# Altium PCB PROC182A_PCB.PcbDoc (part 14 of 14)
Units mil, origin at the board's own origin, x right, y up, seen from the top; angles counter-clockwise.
Board outline 3168.31 x 3700.79 mil, 8 copper layers (Top Layer, L2_GND1, L3_SIG1, L4_PWR1, L5_PWR2, L6_SIG2, L7_GND2, Bottom Layer), stack 58.1 mil thick; 580 components, 391 nets, 8314 pads, 4370 vias.
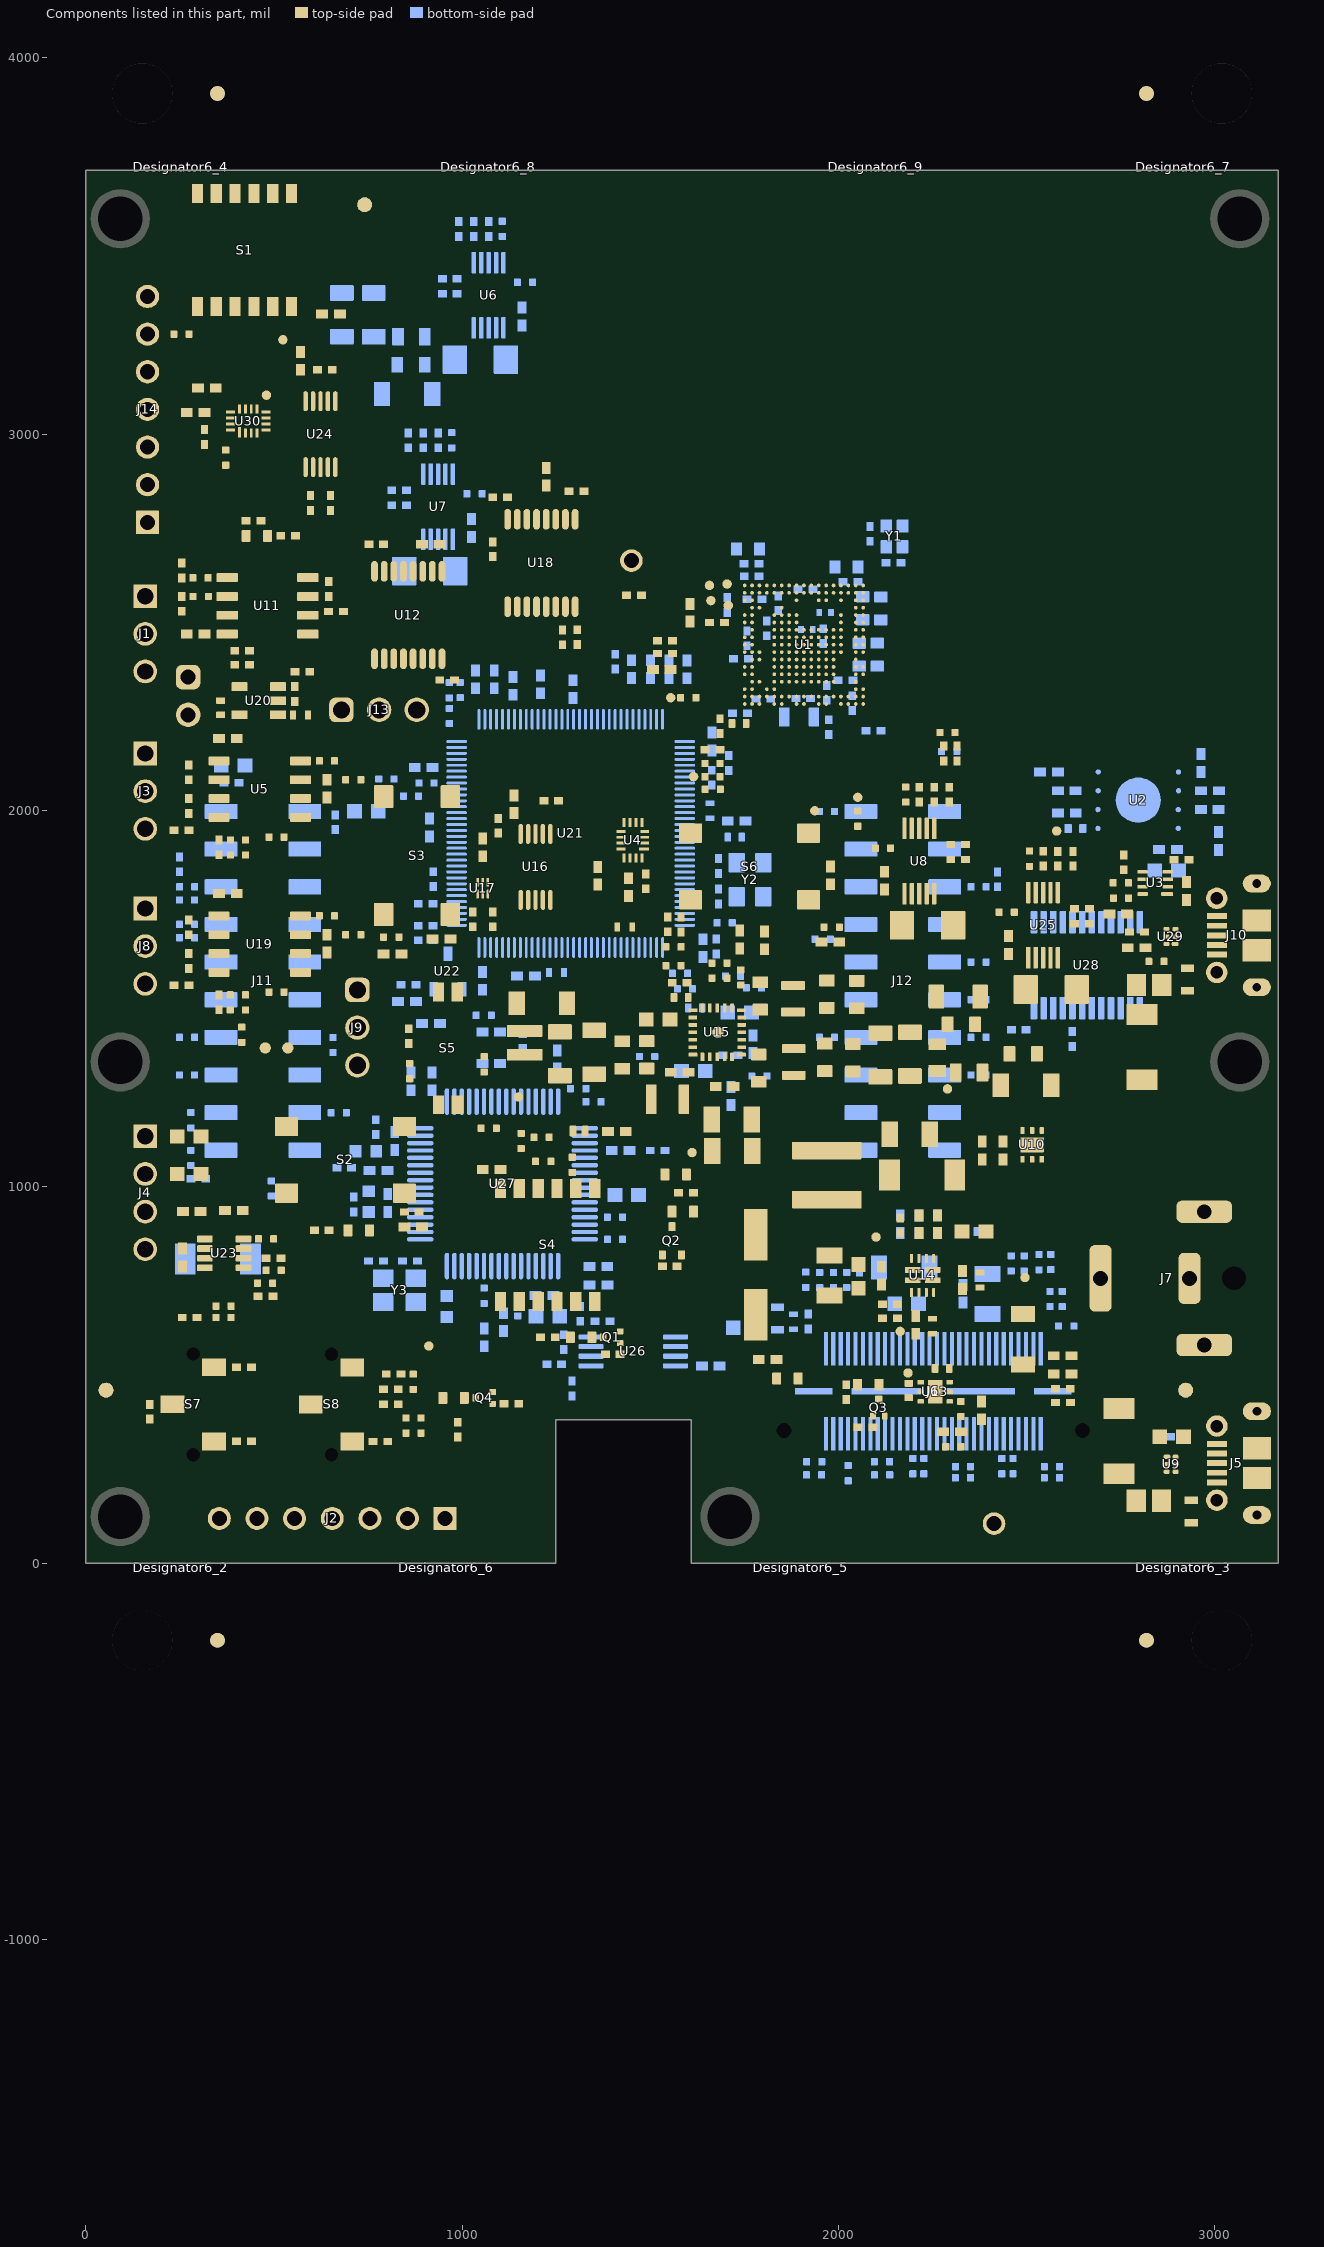
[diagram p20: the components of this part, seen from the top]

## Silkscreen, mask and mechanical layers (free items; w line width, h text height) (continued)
M12 Stackup:
  drawing of 601 lines, arcs and shapes, not listed
  text "NOTE :" at 8331.23,7827.52 h60
  text "1. THIS IS AN IMPEDANCE CONTROLLED BOARD." at 8328.85,7700.44 h60
  text "2. EXTERNAL LAYER CU THICKNESSES ARE FINISHED THICKNESS AFTER PLATING." at 8328.85,7602.57 h60
  text "6" at 10048.98,7447.87 h60
  text "IMPEDANCE TABLE :" at 8892.6,7432.49 h80
  text "LAYER" at 8390.84,7323.14 h70
  text "TRACE WIDTH" at 8678.04,7322.3 h70
  text "SPACING" at 9163.04,7322.3 h70
  text "IMPEDANCE +/- 10%" at 9498.04,7322.3 h70
  text "REFERENCE LAYER" at 10223.04,7322.3 h70
  text "TOP" at 8457.92,7164.16 h70
  text "3.944 MILS" at 9157.24,7164.14 h65
  text "8.386 MILS" at 8742.92,7159.16 h65
  text "50 OHM" at 9617.92,7159.16 h65
  text "LAYER-2 (GND LAYER)" at 10182.92,7159.16 h65
  text "LAYER" at 8389.87,6945.5 h70
  text "TRACE WIDTH" at 8677.07,6944.65 h70
  text "SPACING" at 9162.07,6944.65 h70
  text "IMPEDANCE +/- 10%" at 9497.07,6944.65 h70
  text "REFERENCE LAYER" at 10222.07,6944.65 h70
  text "10.8 MILS" at 8769.81,6782.42 h65
  text "-" at 9289.75,6778.3 h65
  text "LAYER-2" at 10381.3,6776.48 h65
  text "50 OHM" at 9648.9,6773.59 h65
  text "TOP" at 8420.36,6759.04 h70
  text "LAYER-7" at 10376.33,6601.76 h65
  text "-" at 9286.8,6590.31 h65
  text "8.7 MILS" at 8755.67,6583.5 h65
  text "BOTTOM" at 8366.78,6581.81 h60
  text "50 OHM" at 9646.57,6581 h65
  text "6 MILS" at 8757.91,6404.23 h65
  text "50 OHM" at 9646.63,6396.36 h65
  text "L3 & L6" at 8377.39,6392.24 h70
  text "LAYER-2, LAYER 7" at 10253.41,6385.32 h65
  text "LAYER-2" at 10361.75,6229.75 h65
  text "TOP" at 8400.79,6222.36 h70
  text "7.5 MILS" at 8760.59,6212.35 h65
  text "90 OHM" at 9652.66,6211.89 h65
  text "4 MILS" at 9193.85,6210.67 h65
  text "6 MILS" at 8791.86,6049.13 h65
  text "90 OHM" at 9656.08,6044.32 h65
  text "LAYER-7" at 10381.73,6044.87 h65
  text "5 MILS" at 9201.69,6041.6 h65
  text "BOTTOM" at 8396.22,6027.98 h60
  text "5 MILS" at 8790.62,5867.91 h65
  text "90 OHM" at 9662.73,5857.78 h65
  text "5.9 MILS" at 9190.11,5853.43 h65
  text "L3" at 8434.55,5841.85 h70
  text "LAYER-2, LAYER 4" at 10229.8,5836.19 h65
  text "TOP" at 8409.33,5680.06 h70
  text "4.3 MILS" at 8769.14,5670.06 h65
  text "120 OHM" at 9661.21,5669.59 h65
  text "5.5 MILS" at 9202.4,5668.37 h65
  text "LAYER-2" at 10364.71,5659.53 h65
  text "TOP" at 8400.79,5482.36 h70
  text "5.8 MILS" at 8749.74,5477.02 h65
  text "4.2 MILS" at 9183.36,5473.81 h65
  text "100 OHM" at 9641.52,5466.83 h65
  text "LAYER-2" at 10367.12,5465.77 h65
  text "5.9 MILS" at 8752.96,5297.15 h65
  text "100 OHM" at 9634.62,5296.37 h65
  text "3.9 MILS" at 9176.94,5290.72 h65
  text "BOTTOM" at 8396.22,5287.98 h60
  text "LAYER-7" at 10365.97,5283.38 h65
  text "LAYER-2, LAYER 4" at 10252.53,5110.69 h65
  text "L3" at 8434.55,5101.85 h70
  text "4.8 MILS" at 8752.96,5101.21 h65
  text "100 OHM" at 9631.41,5100.44 h65
  text "7.2 MILS" at 9173.73,5088.37 h65
  text "LAYER STACK-UP :" at 3968.15,2059.49 h80
  text "Layer" at 4024.78,1866.38 h60
  text "Name" at 4434.69,1866.38 h60
  text "Material" at 5364.44,1866.38 h60
  text "Thickness" at 6224.2,1866.38 h60
  text "Constant" at 6874.04,1866.38 h60
  text "Board Layer Stack" at 7443.9,1866.38 h60
  text "Top Overlay" at 4434.69,1746.38 h60
  text "Top Solder" at 4434.69,1626.38 h60
  text "Solder Resist" at 5364.44,1626.38 h60
  text "0.80mil" at 6224.2,1626.38 h60
  text "1" at 6874.04,1626.38 h60
  text "1" at 4024.78,1506.38 h60
  text "Top Layer" at 4434.69,1506.38 h60
  text "1.60mil" at 6224.2,1506.38 h60
  text "Dielectric 1" at 4434.69,1386.38 h60
  text "RO3003" at 5364.44,1386.38 h60
  text "5.00mil" at 6224.2,1386.38 h60
  text "3" at 6874.04,1386.38 h60
  text "2" at 4024.78,1266.38 h60
  text "L2_GND1" at 4434.69,1266.38 h60
  text "1.40mil" at 6224.2,1266.38 h60
  text "Dielectric 2" at 4434.69,1146.38 h60
  text "PCL370HR" at 5364.44,1146.38 h60
  text "5.50mil" at 6224.2,1146.38 h60
  text "3.9" at 6874.04,1146.38 h60
  text "3" at 4024.78,1026.38 h60
  text "L3_SIG1" at 4434.69,1026.38 h60
  text "1.40mil" at 6224.2,1026.38 h60
  text "Dielectric 3" at 4434.69,906.38 h60
  text "PCL370HR" at 5364.44,906.38 h60
  text "10.00mil" at 6224.2,906.38 h60
  text "4.25" at 6874.04,906.38 h60
  text "4" at 4024.78,786.38 h60
  text "L4_PWR1" at 4434.69,786.38 h60
  text "1.40mil" at 6224.2,786.38 h60
  text "Dielectric 4" at 4434.69,666.38 h60
  text "PCL370HR" at 5364.44,666.38 h60
  text "5.50mil" at 6224.2,666.38 h60
  text "3.9" at 6874.04,666.38 h60
  text "5" at 4024.78,546.38 h60
  text "L5_PWR2" at 4434.69,546.38 h60
  text "1.40mil" at 6224.2,546.38 h60
  text "Dielectric 5" at 4434.69,426.38 h60
  text "PCL370HR" at 5364.44,426.38 h60
  text "10.00mil" at 6224.2,426.38 h60
  text "4.25" at 6874.04,426.38 h60
  text "6" at 4024.78,306.38 h60
  text "L6_SIG2" at 4434.69,306.38 h60
  text "1.40mil" at 6224.2,306.38 h60
  text "Dielectric 6" at 4434.69,186.38 h60
  text "PCL370HR" at 5364.44,186.38 h60
  text "5.50mil" at 6224.2,186.38 h60
  text "3.9" at 6874.04,186.38 h60
  text "7" at 4024.78,66.38 h60
  text "L7_GND2" at 4434.69,66.38 h60
  text "1.40mil" at 6224.2,66.38 h60
  text "Dielectric 7" at 4434.69,-53.62 h60
  text "PCL370HR" at 5364.44,-53.62 h60
  text "5.00mil" at 6224.2,-53.62 h60
  text "4.25" at 6874.04,-53.62 h60
  text "8" at 4024.78,-173.62 h60
  text "Bottom Layer" at 4434.69,-173.62 h60
  text "1.60mil" at 6224.2,-173.62 h60
  text "Bottom Solder" at 4434.69,-293.62 h60
  text "Solder Resist" at 5364.44,-293.62 h60
  text "0.80mil" at 6224.2,-293.62 h60
  text "1" at 6874.04,-293.62 h60
  text "Bottom Overlay" at 4434.69,-413.62 h60
  text ".Layer_Name" at 186.57,-874.24 h60
M13 Component Bodies Top:
  text ".Layer_Name" at 186.57,-874.24 h60
M14 Component Bodies Bottom:
  text ".Layer_Name" at 186.57,-874.24 h60
M15 Courtyards Top:
  text ".Layer_Name" at 186.57,-874.24 h60
M16 Courtyards Bottom:
  text ".Layer_Name" at 186.57,-874.24 h60
Drill Drawing:
  drawing of 199 lines, arcs and shapes, not listed
  text "Symbol" at -553.46,7687.3 h75.59
  text "Count" at -23.93,7687.3 h75.59
  text "Hole Size" at 667.82,7687.3 h75.59
  text "Plated" at 1747.91,7687.3 h75.59
  text "Hole Type" at 2277.43,7687.3 h75.59
  text "Drill Layer Pair" at 3046.26,7687.3 h75.59
  text "Hole Tolerance (+)" at 4315.27,7687.3 h75.59
  text "Hole Tolerance (-)" at 5713.83,7687.3 h75.59
  text "3453" at -23.93,7529.82 h62.99
  text "7.00mil (0.178mm)" at 667.82,7529.82 h62.99
  text "PTH" at 1747.91,7529.82 h62.99
  text "Round" at 2277.43,7529.82 h62.99
  text "Top Layer - L2_GND1" at 3046.26,7529.82 h62.99
  text "0.00mil (0.000mm)" at 4315.27,7529.82 h62.99
  text "0.00mil (0.000mm)" at 5713.83,7529.82 h62.99
  text "3453 Total" at -23.93,7372.33 h62.99
  text "Symbol" at -528.63,7262.14 h71.39
  text "Count" at -26.74,7262.14 h71.39
  text "Hole Size" at 617.79,7262.14 h71.39
  text "Hole Length" at 1757.95,7262.14 h71.39
  text "Plated" at 2868.38,7262.14 h71.39
  text "Hole Type" at 3370.27,7262.14 h71.39
  text "Drill Layer Pair" at 4098.17,7262.14 h71.39
  text "Hole Tolerance (+)" at 5585.29,7262.14 h71.39
  text "Hole Tolerance (-)" at 6907.95,7262.14 h71.39
  text "2" at -26.74,7113.4 h59.5
  text "7.87mil (0.200mm)" at 617.79,7113.4 h59.5
  text "-" at 1757.95,7113.4 h59.5
  text "PTH" at 2868.38,7113.4 h59.5
  text "Round" at 3370.27,7113.4 h59.5
  text "Top Layer - Bottom Layer" at 4098.17,7113.4 h59.5
  text "4" at -26.74,6964.66 h59.5
  text "7.87mil (0.200mm)" at 617.79,6964.66 h59.5
  text "-" at 1757.95,6964.66 h59.5
  text "PTH" at 2868.38,6964.66 h59.5
  text "Round" at 3370.27,6964.66 h59.5
  text "Top Layer - Bottom Layer" at 4098.17,6964.66 h59.5
  text "3.00mil (0.076mm)" at 5585.29,6964.66 h59.5
  text "3.00mil (0.076mm)" at 6907.95,6964.66 h59.5
  text "911" at -26.74,6815.92 h59.5
  text "8.00mil (0.203mm)" at 617.79,6815.92 h59.5
  text "-" at 1757.95,6815.92 h59.5
  text "PTH" at 2868.38,6815.92 h59.5
  text "Round" at 3370.27,6815.92 h59.5
  text "Top Layer - Bottom Layer" at 4098.17,6815.92 h59.5
  text "3.00mil (0.076mm)" at 5585.29,6815.92 h59.5
  text "3.00mil (0.076mm)" at 6907.95,6815.92 h59.5
  text "24" at -26.74,6667.19 h59.5
  text "19.69mil (0.500mm)" at 617.79,6667.19 h59.5
  text "-" at 1757.95,6667.19 h59.5
  text "NPTH" at 2868.38,6667.19 h59.5
  text "Round" at 3370.27,6667.19 h59.5
  text "Top Layer - Bottom Layer" at 4098.17,6667.19 h59.5
  text "A" at -557.54,6657.2 h66.11
  text "4" at -26.74,6518.45 h59.5
  text "23.62mil (0.600mm)" at 617.79,6518.45 h59.5
  text "51.18mil (1.300mm)" at 1757.95,6518.45 h59.5
  text "PTH" at 2868.38,6518.45 h59.5
  text "Slot" at 3370.27,6518.45 h59.5
  text "Top Layer - Bottom Layer" at 4098.17,6518.45 h59.5
  text "3.00mil (0.076mm)" at 5585.29,6518.45 h59.5
  text "3.00mil (0.076mm)" at 6907.95,6518.45 h59.5
  text "4" at -26.74,6369.71 h59.5
  text "33.47mil (0.850mm)" at 617.79,6369.71 h59.5
  text "-" at 1757.95,6369.71 h59.5
  text "PTH" at 2868.38,6369.71 h59.5
  text "Round" at 3370.27,6369.71 h59.5
  text "Top Layer - Bottom Layer" at 4098.17,6369.71 h59.5
  text "3.00mil (0.076mm)" at 5585.29,6369.71 h59.5
  text "3.00mil (0.076mm)" at 6907.95,6369.71 h59.5
  text "4" at -26.74,6220.97 h59.5
  text "35.43mil (0.900mm)" at 617.79,6220.97 h59.5
  text "-" at 1757.95,6220.97 h59.5
  text "NPTH" at 2868.38,6220.97 h59.5
  text "Round" at 3370.27,6220.97 h59.5
  text "Top Layer - Bottom Layer" at 4098.17,6220.97 h59.5
  text "3.00mil (0.076mm)" at 5585.29,6220.97 h59.5
  text "3.00mil (0.076mm)" at 6907.95,6220.97 h59.5
  text "1" at -26.74,6072.23 h59.5
  text "39.37mil (1.000mm)" at 617.79,6072.23 h59.5
  text "90.55mil (2.300mm)" at 1757.95,6072.23 h59.5
  text "PTH" at 2868.38,6072.23 h59.5
  text "Rectangle" at 3370.27,6072.23 h59.5
  text "Top Layer - Bottom Layer" at 4098.17,6072.23 h59.5
  text "3.00mil (0.076mm)" at 5585.29,6072.23 h59.5
  text "3.00mil (0.076mm)" at 6907.95,6072.23 h59.5
  text "B" at -557.54,6062.24 h66.11
  text "2" at -26.74,5923.49 h59.5
  text "39.37mil (1.000mm)" at 617.79,5923.49 h59.5
  text "98.43mil (2.500mm)" at 1757.95,5923.49 h59.5
  text "PTH" at 2868.38,5923.49 h59.5
  text "Rectangle" at 3370.27,5923.49 h59.5
  text "Top Layer - Bottom Layer" at 4098.17,5923.49 h59.5
  text "3.00mil (0.076mm)" at 5585.29,5923.49 h59.5
  text "3.00mil (0.076mm)" at 6907.95,5923.49 h59.5
  text "C" at -557.54,5913.5 h66.11
  text "1" at -26.74,5774.75 h59.5
  text "39.37mil (1.000mm)" at 617.79,5774.75 h59.5
  text "118.11mil (3.000mm)" at 1757.95,5774.75 h59.5
  text "PTH" at 2868.38,5774.75 h59.5
  text "Rectangle" at 3370.27,5774.75 h59.5
  text "Top Layer - Bottom Layer" at 4098.17,5774.75 h59.5
  text "3.00mil (0.076mm)" at 5585.29,5774.75 h59.5
  text "3.00mil (0.076mm)" at 6907.95,5774.75 h59.5
  text "11" at -26.74,5626.01 h59.5
  text "40.00mil (1.016mm)" at 617.79,5626.01 h59.5
  text "-" at 1757.95,5626.01 h59.5
  text "PTH" at 2868.38,5626.01 h59.5
  text "Round" at 3370.27,5626.01 h59.5
  text "Top Layer - Bottom Layer" at 4098.17,5626.01 h59.5
  text "3.00mil (0.076mm)" at 5585.29,5626.01 h59.5
  text "3.00mil (0.076mm)" at 6907.95,5626.01 h59.5
  text "2" at -26.74,5477.28 h59.5
  text "40.16mil (1.020mm)" at 617.79,5477.28 h59.5
  text "-" at 1757.95,5477.28 h59.5
  text "NPTH" at 2868.38,5477.28 h59.5
  text "Round" at 3370.27,5477.28 h59.5
  text "Top Layer - Bottom Layer" at 4098.17,5477.28 h59.5
  text "3.00mil (0.076mm)" at 5585.29,5477.28 h59.5
  text "3.00mil (0.076mm)" at 6907.95,5477.28 h59.5
  text "7" at -26.74,5328.54 h59.5
  text "40.16mil (1.020mm)" at 617.79,5328.54 h59.5
  text "-" at 1757.95,5328.54 h59.5
  text "PTH" at 2868.38,5328.54 h59.5
  text "Round" at 3370.27,5328.54 h59.5
  text "Top Layer - Bottom Layer" at 4098.17,5328.54 h59.5
  text "3.00mil (0.076mm)" at 5585.29,5328.54 h59.5
  text "3.00mil (0.076mm)" at 6907.95,5328.54 h59.5
  text "13" at -26.74,5179.8 h59.5
  text "43.31mil (1.100mm)" at 617.79,5179.8 h59.5
  text "-" at 1757.95,5179.8 h59.5
  text "PTH" at 2868.38,5179.8 h59.5
  text "Round" at 3370.27,5179.8 h59.5
  text "Top Layer - Bottom Layer" at 4098.17,5179.8 h59.5
  text "3.00mil (0.076mm)" at 5585.29,5179.8 h59.5
  text "3.00mil (0.076mm)" at 6907.95,5179.8 h59.5
  text "6" at -26.74,5031.06 h59.5
  text "45.28mil (1.150mm)" at 617.79,5031.06 h59.5
  text "-" at 1757.95,5031.06 h59.5
  text "PTH" at 2868.38,5031.06 h59.5
  text "Round" at 3370.27,5031.06 h59.5
  text "Top Layer - Bottom Layer" at 4098.17,5031.06 h59.5
  text "3.00mil (0.076mm)" at 5585.29,5031.06 h59.5
  text "3.00mil (0.076mm)" at 6907.95,5031.06 h59.5
  text "1" at -26.74,4882.32 h59.5
  text "62.99mil (1.600mm)" at 617.79,4882.32 h59.5
  text "-" at 1757.95,4882.32 h59.5
  text "NPTH" at 2868.38,4882.32 h59.5
  text "Round" at 3370.27,4882.32 h59.5
  text "Top Layer - Bottom Layer" at 4098.17,4882.32 h59.5
  text "3.00mil (0.076mm)" at 5585.29,4882.32 h59.5
  text "3.00mil (0.076mm)" at 6907.95,4882.32 h59.5
  text "D" at -557.54,4872.33 h66.11
  text "6" at -26.74,4733.58 h59.5
  text "118.11mil (3.000mm)" at 617.79,4733.58 h59.5
  text "-" at 1757.95,4733.58 h59.5
  text "PTH" at 2868.38,4733.58 h59.5
  text "Round" at 3370.27,4733.58 h59.5
  text "Top Layer - Bottom Layer" at 4098.17,4733.58 h59.5
  text "3.00mil (0.076mm)" at 5585.29,4733.58 h59.5
  text "3.00mil (0.076mm)" at 6907.95,4733.58 h59.5
  text "4" at -26.74,4584.84 h59.5
  text "160.00mil (4.064mm)" at 617.79,4584.84 h59.5
  text "-" at 1757.95,4584.84 h59.5
  text "NPTH" at 2868.38,4584.84 h59.5
  text "Round" at 3370.27,4584.84 h59.5
  text "Top Layer - Bottom Layer" at 4098.17,4584.84 h59.5
  text "2.00mil (0.051mm)" at 5585.29,4584.84 h59.5
  text "2.00mil (0.051mm)" at 6907.95,4584.84 h59.5
  text "1007 Total" at -26.74,4436.11 h59.5
  text "Slot definitions :" at -528.63,4292.18 h59.5
  text "Routed Path Length" at 495.61,4292.18 h59.5
  text "= Calculated from tool start centre position to tool end centre position." at 1589.24,4292.18 h59.5
  text "Hole Length" at 495.61,4192.88 h59.5
  text "= Routed Path Length + Tool Size = Slot length as defined in the PCB layout" at 1182.82,4192.88 h59.5
  text ".Layer_Name" at 186.57,-874.24 h60
M17 Embedded Cavity:
  text ".Layer_Name" at 186.57,-874.24 h60
M18 Embedded Assembly:
  text ".Layer_Name" at 186.57,-874.24 h60
M19 Embedded Keepout:
  text ".Layer_Name" at 186.57,-874.24 h60
DCA1000:
  drawing of 10999 lines, arcs and shapes, not listed
6844_ods_rx:
  drawing of 516 lines, arcs and shapes, not listed
PROC074B-PCB_dxf:
  drawing of 11227 lines, arcs and shapes, not listed
6844_ods_tx:
  drawing of 627 lines, arcs and shapes, not listed

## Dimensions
0,4055.13 to 3168.31,4055.13 on M2 Board Dimensions
0,3700.79 to 0,0 on M2 Board Dimensions
0,4055.13 to 0,-354.34 on M2 Board Dimensions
